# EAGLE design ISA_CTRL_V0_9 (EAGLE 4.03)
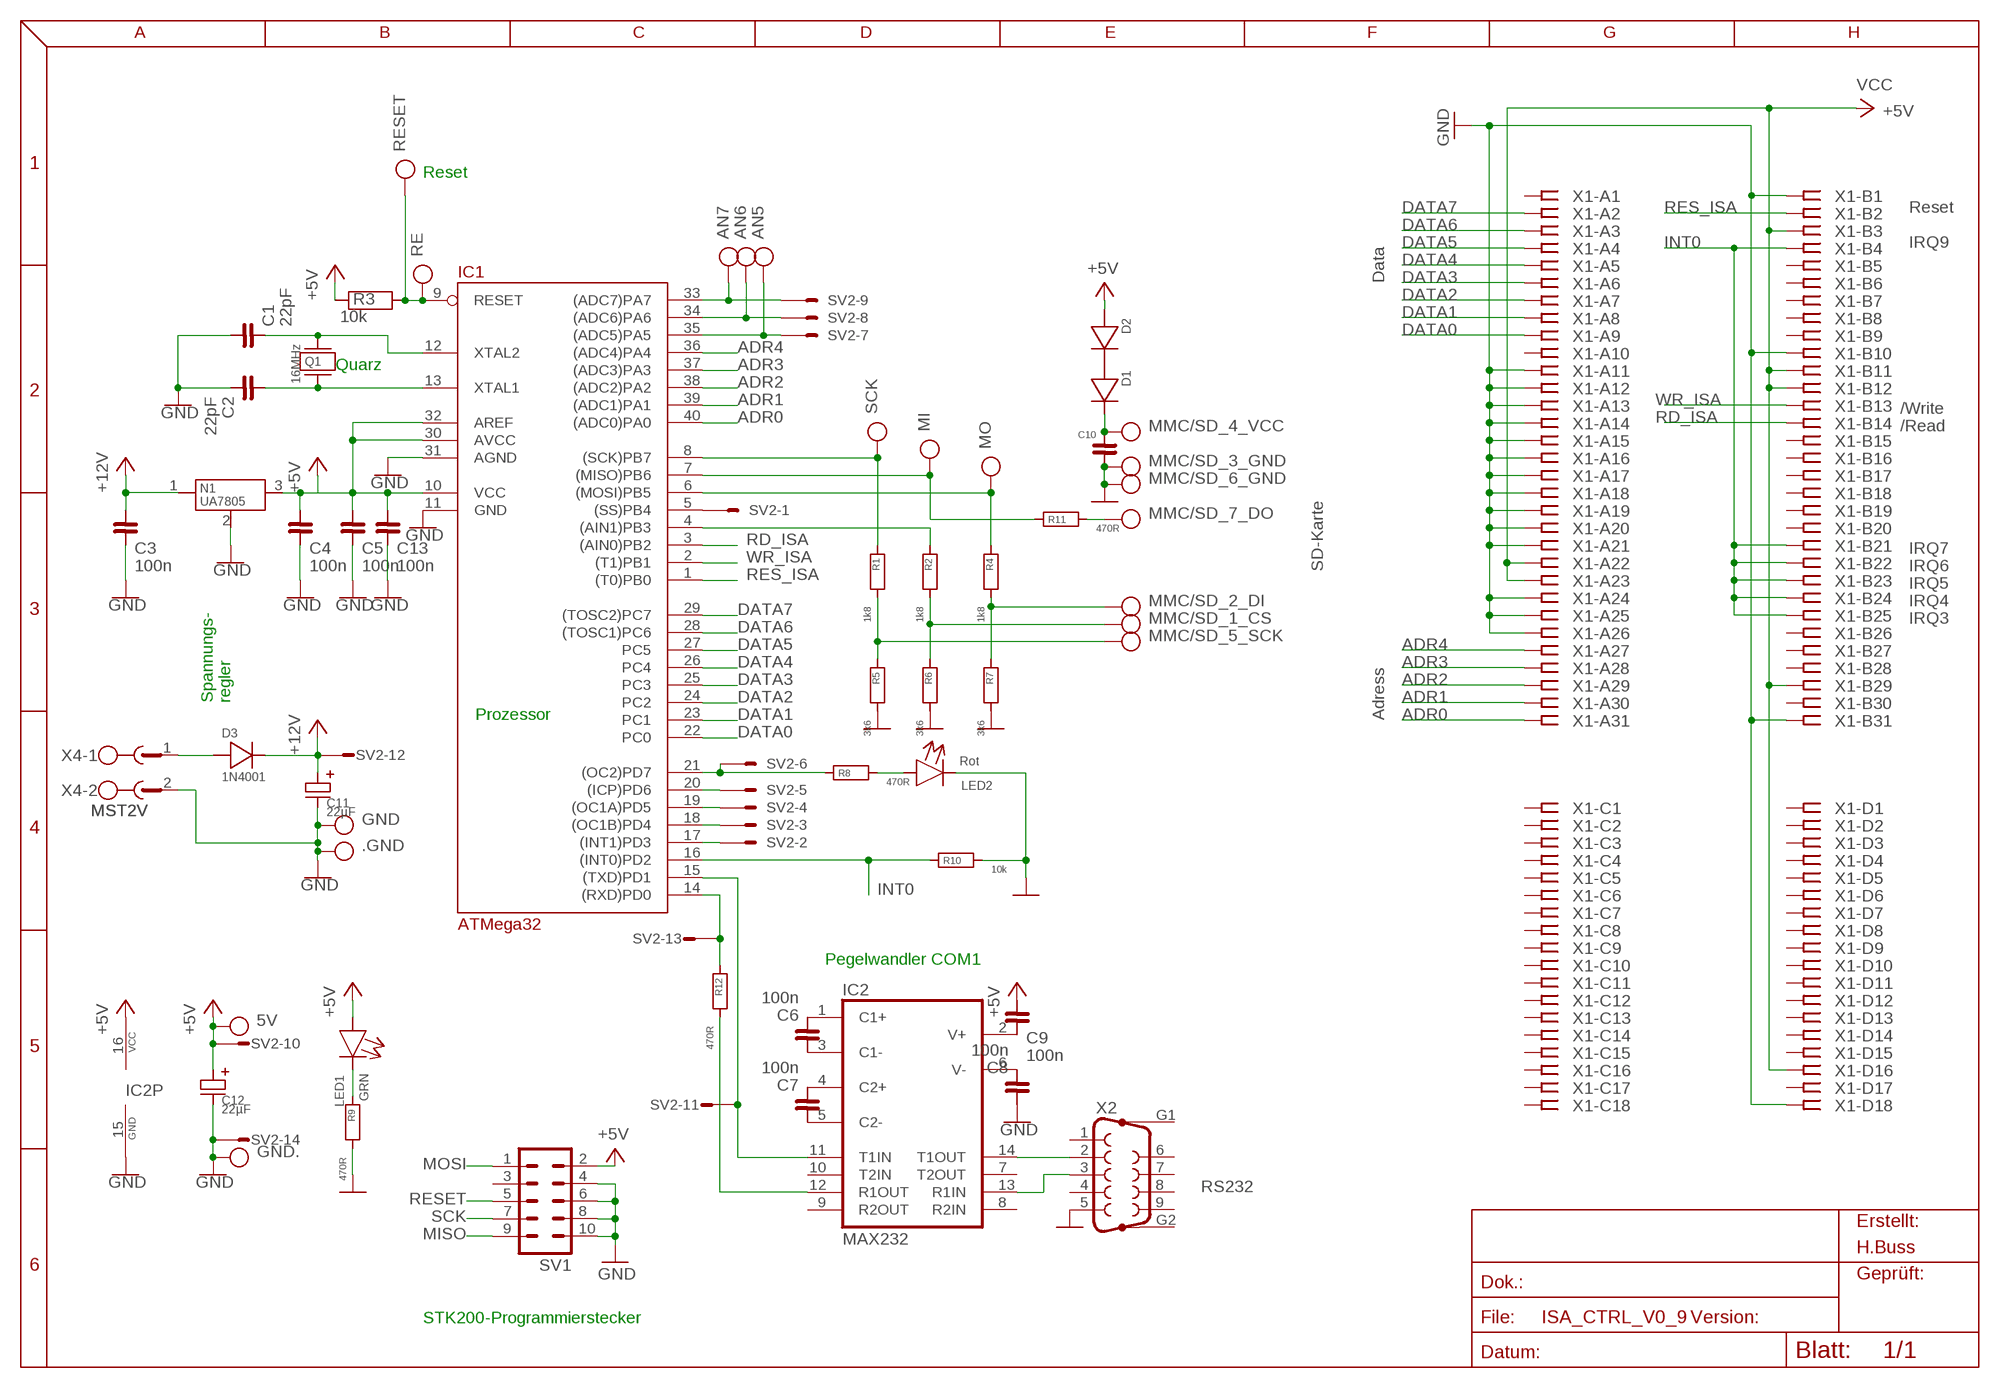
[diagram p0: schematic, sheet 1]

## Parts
5V  PIN_10  [PAD_10]
.GND  PIN_10  [PAD_10]
AN5  PIN_10  [PAD_10]
AN6  PIN_10  [PAD_10]
AN7  PIN_10  [PAD_10]
C1  22pF  C-2,5-MINI  [C-2,5]
C2  22pF  C-2,5-MINI  [C-2,5]
C3  100n  C-5,0  [C-5,0]
C4  100n  C-5,0  [C-5,0]
C5  100n  C-5,0  [C-5,0]
C6  100n  C-5,0  [C-5,0]
C7  100n  C-5,0  [C-5,0]
C8  100n  C-5,0  [C-5,0]
C9  100n  C-5,0  [C-5,0]
C10  C-5,0  [C-5,0]
C11  22µF  2,5-ELKO  [C-2,5-EL]
C12  22µF  2,5-ELKO  [C-2,5-EL]
C13  100n  C-5,0  [C-5,0]
D1  D-10  [D-10]
D2  D-10  [D-10]
D3  1N4001  D-10-1MM  [D-10-1MM]
GND  PIN_08  [PAD_08]
GND.  PIN_10  [PAD_10]
IC1  ATMega32  90S4434-P  [DIL40]
IC2  MAX232  [DIL16]
LED1  GRN  LED_5  [LED_5]
LED2  Rot  LED_5  [LED_5]
MI  PIN_10  [PAD_10]
MMC/SD_1_CS  PIN_081MM  [PAD_10]
MMC/SD_2_DI  PIN_081MM  [PAD_10]
MMC/SD_3_GND  PIN_081MM  [PAD_10]
MMC/SD_4_VCC  PIN_081MM  [PAD_10]
MMC/SD_5_SCK  PIN_081MM  [PAD_10]
MMC/SD_6_GND  PIN_081MM  [PAD_10]
MMC/SD_7_DO  PIN_081MM  [PAD_10]
MO  PIN_10  [PAD_10]
N1  UA7805  UA78XXLIEG  [TO220H]
Q1  16MHz  XTAL-HC18V  [HC-18-V]
R1  1k8  R-10  [R-10]
R2  1k8  R-10  [R-10]
R3  10k  R-10  [R-10]
R4  1k8  R-10  [R-10]
R5  3k6  R-10  [R-10]
R6  3k6  R-10  [R-10]
R7  3k6  R-10  [R-10]
R8  470R  R-10  [R-10]
R9  470R  R-10  [R-10]
R10  10k  R-10  [R-10]
R11  470R  R-10  [R-10]
R12  470R  R-10  [R-10]
RE  PIN_10  [PAD_10]
RESET  PIN_08  [PAD_08]
SCK  PIN_10  [PAD_10]
SV1  ML10  [ML10]
SV2  ML14E  [ML14]
X1  ISA-SLOT  [ISA-16]
X2  F09HP  [F09HP]
X4  MST2V  [MSTBV2]

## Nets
+5V: 5V.P$1(P) C4.P$2 C5.P$2 C9.P$2 C12.MINUS(PLUS) C13.P$2 D2.P$1 IC1.10(VCC) IC1.30(AVCC) IC1.32(AREF) IC2.16(VCC) LED1.A N1.3 R3.P$1 SV1.2 SV2.10 X1.A22 X1.A23 X1.B3 X1.B11 X1.B12 X1.B29 X1.D16 ; supply symbol labelled VCC
+12V: C3.P$2 C11.MINUS(PLUS) D3.P$2 N1.1 SV2.12
ADR0: IC1.40((ADC0)PA0) X1.A31
ADR1: IC1.39((ADC1)PA1) X1.A30
ADR2: IC1.38((ADC2)PA2) X1.A29
ADR3: IC1.37((ADC3)PA3) X1.A28
ADR4: IC1.36((ADC4)PA4) X1.A27
DATA0: IC1.22(PC0) X1.A9
DATA1: IC1.23(PC1) X1.A8
DATA2: IC1.24(PC2) X1.A7
DATA3: IC1.25(PC3) X1.A6
DATA4: IC1.26(PC4) X1.A5
DATA5: IC1.27(PC5) X1.A4
DATA6: IC1.28((TOSC1)PC6) X1.A3
DATA7: IC1.29((TOSC2)PC7) X1.A2
GND: .GND.P$1(P) C1.P$2 C2.P$1 C3.P$1 C4.P$1 C5.P$1 C8.P$2 C10.P$2 C11.PLUS C12.PLUS C13.P$1 GND..P$1(P) GND.P$1(P) IC1.11(GND) IC1.31(AGND) IC2.15(GND) LED2.K MMC/SD_3_GND.P$1(P) MMC/SD_6_GND.P$1(P) N1.2 R5.P$2 R6.P$2 R7.P$2 R9.P$2 R10.P$2 SV1.4 SV1.6 SV1.8 SV1.10 SV2.14 X1.A11 X1.A12 X1.A13 X1.A14 X1.A15 X1.A16 X1.A17 X1.A18 X1.A19 X1.A20 X1.A21 X1.A24 X1.A25 X1.A26 X1.B1 X1.B10 X1.B31 X1.D18 X2.5 X4.2
INT0: IC1.16((INT0)PD2) R10.P$1 X1.B4 X1.B21 X1.B22 X1.B23 X1.B24 X1.B25
MISO: IC1.7((MISO)PB6) MI.P$1(P) R11.P$1 SV1.9
MOSI: IC1.6((MOSI)PB5) MO.P$1(P) R4.P$1 SV1.1
N$1: C10.P$1 D1.P$2 MMC/SD_4_VCC.P$1(P)
N$2: MMC/SD_2_DI.P$1(P) R4.P$2 R7.P$1
N$3: MMC/SD_5_SCK.P$1(P) R1.P$2 R5.P$1
N$4: IC1.4((AIN1)PB3) R2.P$1
N$5: MMC/SD_1_CS.P$1(P) R2.P$2 R6.P$1
N$6: D1.P$1 D2.P$2
N$7: LED1.K R9.P$1
N$8: LED2.A R8.P$2
N$9: MMC/SD_7_DO.P$1(P) R11.P$2
N$10: IC1.17((INT1)PD3) SV2.2
N$11: AN5.P$1(P) IC1.35((ADC5)PA5) SV2.7
N$12: AN6.P$1(P) IC1.34((ADC6)PA6) SV2.8
N$13: AN7.P$1(P) IC1.33((ADC7)PA7) SV2.9
N$14: IC1.18((OC1B)PD4) SV2.3
N$15: IC1.5((SS)PB4) SV2.1
N$16: IC1.21((OC2)PD7) R8.P$1 SV2.6
N$17: IC1.19((OC1A)PD5) SV2.4
N$18: IC1.20((ICP)PD6) SV2.5
N$33: IC2.12(R1OUT) R12.P$2
N$34: C2.P$2 IC1.13(XTAL1) Q1.2
N$35: C1.P$1 IC1.12(XTAL2) Q1.1
N$36: IC2.14(T1OUT) X2.2
N$37: IC2.13(R1IN) X2.3
N$47: C6.P$1 IC2.1(C1+)
N$48: C6.P$2 IC2.3(C1-)
N$49: C7.P$1 IC2.4(C2+)
N$50: C7.P$2 IC2.5(C2-)
N$51: C8.P$1 IC2.6(V-)
N$52: C9.P$1 IC2.2(V+)
N$68: D3.P$1 X4.1
RD_ISA: IC1.3((AIN0)PB2) X1.B14
RES_ISA: IC1.1((T0)PB0) X1.B2
RESET: IC1.9(RESET) R3.P$2 RE.P$1(P) RESET.P$1(P) SV1.5
RXD: IC1.14((RXD)PD0) R12.P$1 SV2.13
SCK: IC1.8((SCK)PB7) R1.P$1 SCK.P$1(P) SV1.7
TXD: IC1.15((TXD)PD1) IC2.11(T1IN) SV2.11
WR_ISA: IC1.2((T1)PB1) X1.B13
Unconnected: IC2.7(T2OUT) IC2.8(R2IN) IC2.9(R2OUT) IC2.10(T2IN) SV1.3 X1.A1 X1.A10 X1.B5 X1.B6 X1.B7 X1.B8 X1.B9 X1.B15 X1.B16 X1.B17 X1.B18 X1.B19 X1.B20 X1.B26 X1.B27 X1.B28 X1.B30 X1.C1 X1.C2 X1.C3 X1.C4 X1.C5 X1.C6 X1.C7 X1.C8 X1.C9 X1.C10 X1.C11 X1.C12 X1.C13 X1.C14 X1.C15 X1.C16 X1.C17 X1.C18 X1.D1 X1.D2 X1.D3 X1.D4 X1.D5 X1.D6 X1.D7 X1.D8 X1.D9 X1.D10 X1.D11 X1.D12 X1.D13 X1.D14 X1.D15 X1.D17 X2.1 X2.4 X2.6 X2.7 X2.8 X2.9 X2.G1 X2.G2

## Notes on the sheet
- Reset
- Reset
- IRQ9
- Data
- Quarz
- /Write
- /Read
- IRQ7
- SD-Karte | IRQ6
- IRQ5
- IRQ4
- IRQ3
- Spannungs- | regler
- Prozessor | Adress
- Pegelwandler COM1
- RS232
- STK200-Programmierstecker

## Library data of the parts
5V .GND AN5-AN7 GND. = 0MY_STD_LIB:PIN_10
C1 C2 = MY_STD_L:C-2,5-MINI
C3-C9 C13 = MY_STD_L:C-5,0
C10 = 0MY_STD_LIB:C-5,0
C11 C12 = MY_STD_L:2,5-ELKO
D1 D2 = 0MY_STD_LIB:D-10
D3 = MY_STD_L:D-10-1MM
GND MMC/SD_1_CS MMC/SD_2_DI MMC/SD_3_GND MMC/SD_4_VCC MMC/SD_5_SCK MMC/SD_6_GND MMC/SD_7_DO = 0MY_STD_LIB:PIN_08
IC1 = ATMEL_:90S4434-P
IC2 = MAXIM:MAX232
LED1 LED2 = 0MY_STD_LIB:LED_5
MI MO RE SCK = MY_STD_L:PIN_10
N1 = MY_STD_L:UA78XXLIEG
Q1 = MY_STD_L:XTAL-HC18V
R1 R2 R4-R12 = 0MY_STD_LIB:R-10
R3 = MY_STD_L:R-10
RESET = MY_STD_L:PIN_08
SV1 = CON-ML:ML10
SV2 = CON-ML:ML14E
X1 = con-pc:ISA-SLOT: ISA SLOT
X2 = con-subd:F09HP: HARTING SUB-D
X4 = con-phoenix-508:MST2V: PHOENIX

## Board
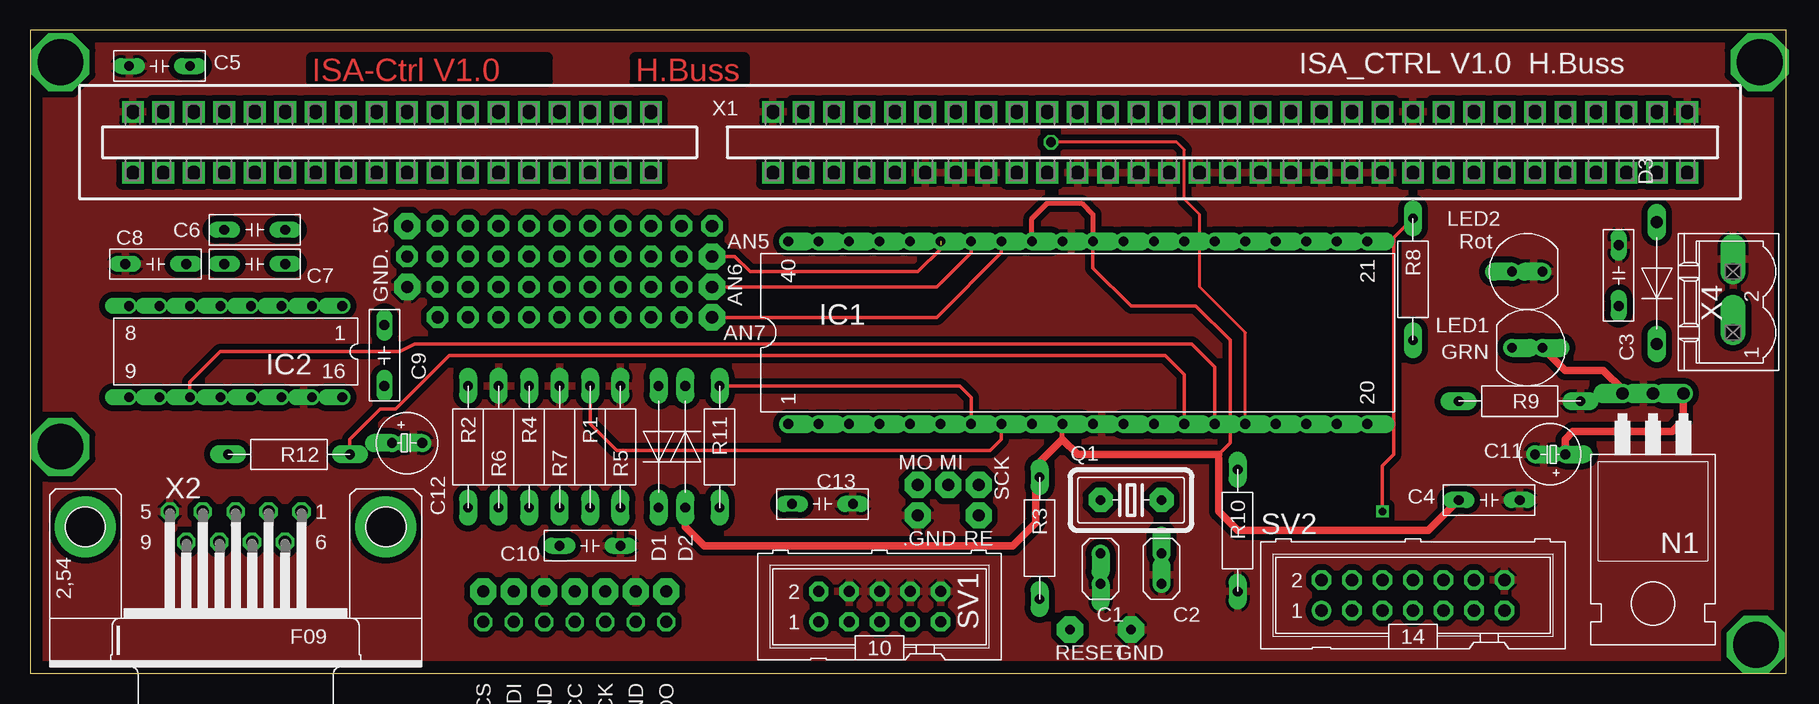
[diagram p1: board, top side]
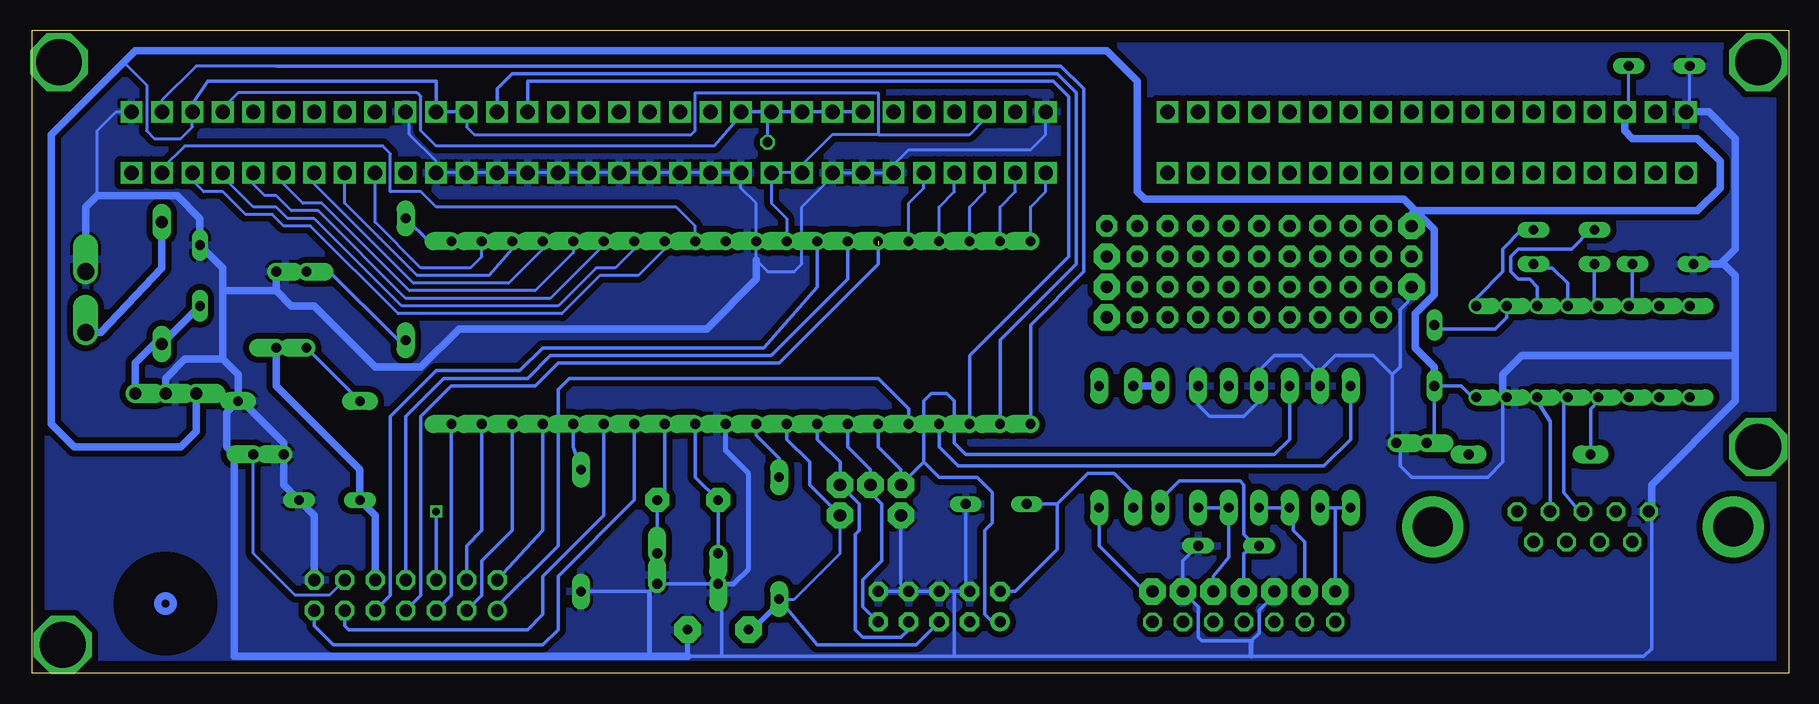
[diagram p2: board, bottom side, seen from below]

Size 146.35 x 53.64 mm. Coordinates in mm from the lower left corner, seen from the top.
Outline: 0,0 146.35,0 146.35,53.64 0,53.64 0,0
Copper layers used: Top, Bottom

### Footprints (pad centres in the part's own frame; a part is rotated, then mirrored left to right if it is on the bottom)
PAD_10 = drill 1.016 pad 2.184 octagon: P$1 0,0
C-2,5 = drill 0.813 pad 1.5 offset: P$1 0,0; P$2 2.54,0
C-5,0 = drill 0.813 pad 1.27 long: P$1 0,0; P$2 5.08,0
C-2,5-EL = drill 0.813 pad 1.5 offset: MINUS 2.54,0; PLUS 0,0
D-10 = drill 0.813 pad 1.5 long: P$1 0,0; P$2 10.16,0
D-10-1MM = drill 1.016 pad 1.5 long: P$1 -1.27,0; P$2 8.89,0
PAD_08 = drill 0.813 pad 2.184 octagon: P$1 0,0
DIL40 = drill 0.813 pad 1.5 offset: 1 -24.13,-7.62; 2 -21.59,-7.62; 3 -19.05,-7.62; 4 -16.51,-7.62; 5 -13.97,-7.62; 6 -11.43,-7.62; 7 -8.89,-7.62; 8 -6.35,-7.62; 9 -3.81,-7.62; 10 -1.27,-7.62; 11 1.27,-7.62; 12 3.81,-7.62; 13 6.35,-7.62; 14 8.89,-7.62; 15 11.43,-7.62; 16 13.97,-7.62; 17 16.51,-7.62; 18 19.05,-7.62; 19 21.59,-7.62; 20 24.13,-7.62; 21 24.13,7.62; 22 21.59,7.62; 23 19.05,7.62; 24 16.51,7.62; 25 13.97,7.62; 26 11.43,7.62; 27 8.89,7.62; 28 6.35,7.62; 29 3.81,7.62; 30 1.27,7.62; 31 -1.27,7.62; 32 -3.81,7.62; 33 -6.35,7.62; 34 -8.89,7.62; 35 -11.43,7.62; 36 -13.97,7.62; 37 -16.51,7.62; 38 -19.05,7.62; 39 -21.59,7.62; 40 -24.13,7.62
DIL16 = drill 0.813 pad 1.27 offset: 1 -8.89,-3.81; 2 -6.35,-3.81; 3 -3.81,-3.81; 4 -1.27,-3.81; 5 1.27,-3.81; 6 3.81,-3.81; 7 6.35,-3.81; 8 8.89,-3.81; 9 8.89,3.81; 10 6.35,3.81; 11 3.81,3.81; 12 1.27,3.81; 13 -1.27,3.81; 14 -3.81,3.81; 15 -6.35,3.81; 16 -8.89,3.81
LED_5 = drill 0.813 pad 1.5 offset: A 1.27,0; K -1.27,0
TO220H = drill 1.016 pad 1.626 offset: 1 0,0; 2 2.54,0; 3 5.08,0
HC-18-V = drill 0.813 pad 2 octagon: 1 0,0; 2 5.08,0
R-10 = drill 0.813 pad 1.5 long: P$1 0,0; P$2 10.16,0
ML10 = drill 0.914 pad 1.6 round: 1 -5.08,-1.27 | drill 0.914 pad 1.6 octagon: 2 -5.08,1.27; 3 -2.54,-1.27; 4 -2.54,1.27; 5 0,-1.27; 6 0,1.27; 7 2.54,-1.27; 8 2.54,1.27; 9 5.08,-1.27; 10 5.08,1.27
ML14 = drill 1.016 pad 1.6 round: 1 -7.62,-1.27 | drill 1.016 pad 1.6 octagon: 2 -7.62,1.27; 3 -5.08,-1.27; 4 -5.08,1.27; 5 -2.54,-1.27; 6 -2.54,1.27; 7 0,-1.27; 8 0,1.27; 9 2.54,-1.27; 10 2.54,1.27; 11 5.08,-1.27; 12 5.08,1.27; 13 7.62,-1.27; 14 7.62,1.27
ISA-16 = drill 1.2 pad 1.778 square: A1 81.28,-2.54; A2 78.74,-2.54; A3 76.2,-2.54; A4 73.66,-2.54; A5 71.12,-2.54; A6 68.58,-2.54; A7 66.04,-2.54; A8 63.5,-2.54; A9 60.96,-2.54; A10 58.42,-2.54; A11 55.88,-2.54; A12 53.34,-2.54; A13 50.8,-2.54; A14 48.26,-2.54; A15 45.72,-2.54; A16 43.18,-2.54; A17 40.64,-2.54; A18 38.1,-2.54; A19 35.56,-2.54; A20 33.02,-2.54; A21 30.48,-2.54; A22 27.94,-2.54; A23 25.4,-2.54; A24 22.86,-2.54; A25 20.32,-2.54; A26 17.78,-2.54; A27 15.24,-2.54; A28 12.7,-2.54; A29 10.16,-2.54; A30 7.62,-2.54; A31 5.08,-2.54; B1 81.28,2.54; B2 78.74,2.54; B3 76.2,2.54; B4 73.66,2.54; B5 71.12,2.54; B6 68.58,2.54; B7 66.04,2.54; B8 63.5,2.54; B9 60.96,2.54; B10 58.42,2.54; B11 55.88,2.54; B12 53.34,2.54; B13 50.8,2.54; B14 48.26,2.54; B15 45.72,2.54; B16 43.18,2.54; B17 40.64,2.54; B18 38.1,2.54; B19 35.56,2.54; B20 33.02,2.54; B21 30.48,2.54; B22 27.94,2.54; B23 25.4,2.54; B24 22.86,2.54; B25 20.32,2.54; B26 17.78,2.54; B27 15.24,2.54; B28 12.7,2.54; B29 10.16,2.54; B30 7.62,2.54; B31 5.08,2.54; C1 -5.08,-2.54; C2 -7.62,-2.54; C3 -10.16,-2.54; C4 -12.7,-2.54; C5 -15.24,-2.54; C6 -17.78,-2.54; C7 -20.32,-2.54; C8 -22.86,-2.54; C9 -25.4,-2.54; C10 -27.94,-2.54; C11 -30.48,-2.54; C12 -33.02,-2.54; C13 -35.56,-2.54; C14 -38.1,-2.54; C15 -40.64,-2.54; C16 -43.18,-2.54; C17 -45.72,-2.54; C18 -48.26,-2.54; D1 -5.08,2.54; D2 -7.62,2.54; D3 -10.16,2.54; D4 -12.7,2.54; D5 -15.24,2.54; D6 -17.78,2.54; D7 -20.32,2.54; D8 -22.86,2.54; D9 -25.4,2.54; D10 -27.94,2.54; D11 -30.48,2.54; D12 -33.02,2.54; D13 -35.56,2.54; D14 -38.1,2.54; D15 -40.64,2.54; D16 -43.18,2.54; D17 -45.72,2.54; D18 -48.26,2.54
F09HP = drill 1.016 octagon: 1 -5.486,-1.27; 2 -2.743,-1.27; 3 0,-1.27; 4 2.743,-1.27; 5 5.486,-1.27; 6 -4.115,1.27; 7 -1.372,1.27; 8 1.372,1.27; 9 4.115,1.27 | drill 3.302 pad 5.08 round: G1 -12.522,0; G2 12.522,0
MSTBV2 = drill 1.397 offset: 1 -2.54,0; 2 2.54,0

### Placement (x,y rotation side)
5V  31.43,37.3 0 top
.GND  73.97,13.17 0 top
AN5  56.83,34.76 0 top
AN6  56.83,32.22 0 top
AN7  56.83,29.68 0 top
C1  89.21,9.99 270 top
C2  94.29,7.45 90 top
C3  132.39,35.71 270 top
C4  124.14,14.44 180 top
C5  8.25,50.64 0 top
C6  21.27,36.98 180 top
C7  21.27,34.12 180 top
C8  13.01,34.12 180 top
C9  29.52,29.05 270 top
C10  44.13,10.63 0 top
C11  125.41,18.25 0 top
C12  32.7,19.2 180 top
C13  68.58,14.12 180 top
D1  52.38,23.97 270 top
D2  54.61,13.8 90 top
D3  135.57,36.35 270 top
GND  91.75,3.64 0 top
GND.  31.43,32.22 0 top
IC1  87.31,28.41 0 top
IC2  17.14,26.82 180 top
LED1  124.77,27.14 0 top
LED2  124.77,33.49 180 top
MI  76.51,15.71 180 top
MMC/SD_1_CS  37.78,6.82 0 top
MMC/SD_2_DI  40.32,6.82 270 top
MMC/SD_3_GND  42.86,6.82 270 top
MMC/SD_4_VCC  45.4,6.82 270 top
MMC/SD_5_SCK  47.94,6.82 270 top
MMC/SD_6_GND  50.48,6.82 270 top
MMC/SD_7_DO  53.02,6.82 270 top
MO  73.97,15.71 180 top
N1  137.79,23.33 180 top
Q1  89.21,14.44 0 top
R1  46.67,23.97 270 top
R2  36.51,23.97 270 top
R3  84.13,16.34 270 top
R4  41.59,23.97 270 top
R5  49.21,13.8 90 top
R6  39.05,13.8 90 top
R7  44.13,13.8 90 top
R8  115.25,37.94 270 top
R9  119.06,22.69 0 top
R10  100.64,16.98 270 top
R11  57.46,23.97 270 top
R12  26.67,18.25 180 top
RE  79.05,13.17 0 top
RESET  86.67,3.64 0 top
SCK  79.05,15.71 90 top
SV1  70.8,5.55 0 top
SV2  115.25,6.5 0 top
X1  56.83,44.28 0 top
X2  17.14,12.22 180 top
X4  141.92,30.95 90 top

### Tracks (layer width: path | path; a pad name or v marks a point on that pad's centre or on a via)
+5V
  Top 0.305: 99.06,18.25 100.01,19.2 100.01,27.78 97.15,30.63 91.75,30.63 88.58,33.81 IC1.30
  Top 0.406: IC1.32 83.5,37.94 84.77,39.2 87.62,39.2 88.58,38.25 IC1.30 | 86.04,19.52 IC1.10
  Top 0.61: 99.06,18.25 87.31,18.25 86.04,19.52 84.13,17.61 R3.P$1 83.81,16.03 83.81,12.53 81.91,10.63 56.19,10.63 54.61,12.22 D2.P$1 54.61,14.12 | N1.3 132.71,23.65 131.12,25.23 127.95,25.23 LED1.A | 99.06,17.93 99.06,13.49 100.64,11.9 116.52,11.9 C4.P$2
  Bottom 0.254: X1.B29 66.99,46.19 68.26,44.92 75.88,44.92 | 75.88,44.92 79.69,44.92 82.23,42.38 X1.A23 X1.A22 | X1.A22 84.77,39.2 83.5,37.94 IC1.32 | X1.A22 85.4,41.75 | 75.88,44.92 75.88,48.41 91.12,48.41 91.12,45.24 91.43,44.92 109.53,44.92 110.17,45.55 X1.B12 | 138.74,50.95 136.84,49.05 136.84,45.24 136.2,44.6 133.98,44.6 133.03,45.55 X1.B3 | C5.P$2 13.33,47.14 X1.D16
  Bottom 0.305: X1.B12 X1.B11 112.71,49.36 131.76,49.36 133.03,47.46 X1.B3 | IC2.16 26.03,22.69 27.3,23.97 C9.P$2 29.52,19.84 C12.MINUS | D2.P$1 54.61,15.07 56.19,16.66 58.42,16.66 60.95,14.12 | 60.95,14.12 60.95,10.31 64.45,6.82 SV1.2 | R3.P$1 84.13,17.93 86.04,19.84 IC1.10 | 60.95,14.12 C13.P$2
  Bottom 0.61: X1.D16 13.65,45.24 13.01,44.6 7.62,44.6 5.71,42.7 5.71,40.47 7.62,38.57 31.11,38.57 | 31.11,38.57 32.06,39.52 53.65,39.52 54.29,40.16 54.29,49.36 56.83,51.91 137.79,51.91 138.74,50.95 144.77,44.92 144.77,20.79 142.87,18.89 133.98,18.89 132.71,20.16 N1.3 | SV2.10 117.79,13.17 C4.P$2 119.06,16.98 126.04,23.97 LED1.A | C9.P$2 29.52,25.55 31.11,27.14 31.11,30 29.52,31.58 29.52,36.98 31.11,38.57 | 5V.P$1 31.75,37.94 31.11,38.57
+12V
  Top 0.61: C11.MINUS 127.95,19.52 128.58,20.16 136.84,20.16 137.79,21.11 N1.1
  Bottom 0.254: C11.MINUS 127.95,9.99 124.45,6.5 121.6,6.5 SV2.12
  Bottom 0.61: C3.P$2 D3.P$2 136.2,27.46 137.79,25.87 N1.1
ADR0
  Bottom 0.254: X1.A31 61.91,40.16 63.18,38.89 IC1.40
ADR1
  Bottom 0.254: X1.A30 64.45,40.16 65.72,38.89 IC1.39
ADR2
  Bottom 0.254: X1.A29 66.99,40.16 68.26,38.89 IC1.38
ADR3
  Bottom 0.254: X1.A28 69.53,40.16 70.8,38.89 IC1.37
ADR4
  Bottom 0.254: X1.A27 72.07,40.47 73.34,39.2 IC1.36
DATA0
  Bottom 0.254: IC1.22 108.9,34.76 109.85,33.81 113.98,33.81 117.79,37.62 X1.A9
DATA1
  Bottom 0.254: IC1.23 106.36,35.39 108.26,33.17 114.29,33.17 120.33,39.2 X1.A8
DATA2
  Bottom 0.254: IC1.24 103.82,35.39 106.67,32.54 114.61,32.54 122.87,40.79 X1.A7
DATA3
  Bottom 0.254: IC1.25 101.28,35.08 104.45,31.9 114.93,31.9 122.23,39.2 123.82,39.2 125.41,40.79 X1.A6
DATA4
  Bottom 0.254: IC1.26 98.74,35.71 103.18,31.27 115.25,31.27 122.55,38.57 124.77,38.57 126.04,39.84 126.99,39.84 127.95,40.79 X1.A5
DATA5
  Bottom 0.254: IC1.27 96.2,35.39 97.79,33.81 99.37,33.81 102.55,30.63 115.57,30.63 122.87,37.94 125.09,37.94 126.04,38.89 127.95,38.89 130.49,41.43 X1.A4
DATA6
  Bottom 0.254: IC1.28 93.66,35.39 95.88,33.17 99.06,33.17 102.23,30 115.88,30 123.19,37.3 125.41,37.3 126.36,38.25 128.58,38.25 130.49,40.16 132.07,40.16 133.03,41.11 X1.A3
DATA7
  Bottom 0.254: IC1.29 91.12,37.3 92.7,38.89 112.71,38.89 113.98,40.16 116.52,40.16 116.52,43.33 117.15,43.97 133.66,43.97 135.57,42.06 X1.A2
GND
  Bottom 0.254: X1.B31 61.91,44.92 63.18,43.65 73.34,43.65 74.61,42.38 X1.A26 X1.A25 X1.A24 | X1.A24 79.69,41.11 | X1.B10 114.93,46.51 114.93,44.92 112.71,42.7 X1.A11 X1.A12 X1.A13 X1.A14 X1.A15 | X1.B1 139.38,46.83 140.97,45.24 140.97,39.84 | X1.A24 79.69,41.43 82.23,38.89 82.23,34.12 82.86,33.49 85.09,33.49 86.04,34.44 IC1.31 86.04,39.2 87.31,40.47 X1.A21 X1.A20 X1.A19 X1.A18 X1.A17 X1.A16 X1.A15 | X1.A15 102.87,41.75 | C5.P$1 8.25,47.14 X1.D18
  Bottom 0.305: R10.P$2 94.93,6.82 C2.P$1 C1.P$2 88.9,7.14 88.9,1.42 | 69.53,6.82 SV1.6 SV1.8 | SV1.8 SV1.10 | .GND.P$1 73.97,7.45 SV1.8 | 69.53,6.82 SV1.4 68.57,7.14 C13.P$1 | 69.53,1.42 69.53,6.82 | 69.53,1.42 88.9,1.42 | 69.53,1.42 44.76,1.42 12.06,1.42 11.43,2.06 11.43,14.12 | IC2.15 23.81,23.01 23.81,17.61 25.08,16.34 31.43,16.34 32.38,17.3 32.38,18.89 C12.PLUS 33.01,19.52 33.01,24.92 | MMC/SD_3_GND.P$1 42.86,6.5 44.13,5.23 44.13,3.33 44.76,2.69 48.89,2.69 49.21,3.01 49.21,5.55 MMC/SD_6_GND.P$1 50.48,9.36 C10.P$2 | R5.P$2 49.21,22.38 48.26,21.42 45.4,21.42 44.13,22.69 R7.P$2 44.13,25.23 42.86,26.5 40.64,26.5 39.05,24.92 R6.P$2 39.05,25.23 37.78,26.5 34.6,26.5 33.01,24.92 | 88.9,1.42 91.75,1.42 | GND..P$1 31.75,30.95 32.38,30.31 32.38,25.55 33.01,24.92
  Bottom 0.406: IC1.11 88.58,18.57 86.67,16.66 86.67,8.73 87.94,7.45 C1.P$2 | 91.75,1.42 GND.P$1 | 94.93,1.42 94.93,6.82 | 44.76,1.42 44.76,2.69
  Bottom 0.61: 5.71,34.12 5.39,34.12 4.44,33.17 4.44,26.5 | 5.71,34.12 C8.P$2 | 4.44,26.5 4.44,22.69 11.43,15.71 11.43,14.12 X2.5 | X1.D18 6.66,46.83 4.44,44.6 4.44,35.39 5.71,34.12 | 23.81,23.01 23.81,24.92 22.22,26.5 4.44,26.5 | R9.P$2 129.22,23.01 125.41,19.2 C11.PLUS 125.41,15.71 C4.P$1 122.87,13.17 SV2.14 | 130.49,26.19 130.49,31.9 | 130.49,26.19 133.66,26.19 135.25,24.6 N1.2 135.25,23.01 | R9.P$2 129.22,24.92 130.49,26.19 | R9.P$2 130.17,21.74 130.17,18.89 129.54,18.25 129.54,1.42 94.93,1.42 91.75,1.42 | 86.04,34.44 86.04,32.86 90.17,28.73 110.8,28.73 113.98,25.55 117.79,25.55 122.87,30.63 124.77,30.63 126.04,31.9 | 126.04,31.9 LED2.K | 130.49,31.9 126.04,31.9 | 130.49,31.9 130.49,33.81 C3.P$1 132.39,37.94 134.3,39.84 140.97,39.84 141.92,38.89 X4.2
  pour Top (isolate 0.5): 0.63,52.86 0.63,0.79 146.04,0.47 146.36,52.86
  pour Bottom (isolate 0.5): 0.63,52.86 0.63,0.79 145.73,0.79 146.04,52.86
INT0  (via drill 0.81)
  Top 0.254: IC1.16 101.28,28.41 97.47,32.22 97.47,38.25 96.2,39.52 96.2,43.65 95.56,44.28 v85.09,44.28
  Bottom 0.254: X1.B21 87.31,46.51 89.53,43.97 112.71,43.97 113.98,45.24 113.98,48.09 114.29,48.41 129.22,48.41 130.49,47.14 X1.B4 | v85.09,44.28 85.09,46.51 X1.B22
  Bottom 0.305: X1.B25 X1.B24 X1.B23 X1.B22 X1.B21 | R10.P$1 101.28,18.89 IC1.16
MISO
  Top 0.305: R11.P$1 77.46,23.97 78.42,23.01 IC1.7
  Bottom 0.305: IC1.7 78.42,18.89 76.51,16.98 MI.P$1 76.51,15.07 75.56,14.12 75.56,9.36 77.15,7.77 77.15,5.55 SV1.9
MOSI
  Bottom 0.305: IC1.6 75.88,18.89 73.97,16.98 MO.P$1 72.07,17.61 | SV1.1 66.35,4.28 66.99,4.91 66.99,11.9 66.35,12.53 66.35,15.07 67.62,16.34 70.8,16.34 72.07,17.61 | R4.P$1 41.59,19.52 42.86,18.25 68.57,18.25 69.53,19.2 69.53,22.69 70.16,23.33 71.43,23.33 72.07,22.69 72.07,17.61
N$1
  Bottom 0.305: D1.P$2 52.38,14.44 50.79,16.03 45.71,16.03 45.4,15.71 45.4,11.58 44.45,10.63 C10.P$1 45.4,9.99 MMC/SD_4_VCC.P$1
N$2
  Bottom 0.305: MMC/SD_2_DI.P$1 40.32,10.95 41.27,11.9 41.27,13.49 R4.P$2 R7.P$1
N$3
  Bottom 0.305: MMC/SD_5_SCK.P$1 47.94,8.09 46.67,9.68 R1.P$2 R5.P$1
N$4
  Bottom 0.305: R2.P$1 36.51,19.52 38.73,17.3 69.21,17.3 70.8,18.89 IC1.4
N$5
  Bottom 0.305: MMC/SD_1_CS.P$1 37.78,13.8 | 37.78,13.8 R2.P$2 | 37.78,13.8 R6.P$1
N$6
  Bottom 0.61: D1.P$1 D2.P$2
N$7
  Bottom 0.305: R9.P$1 LED1.K
N$8
  Bottom 0.305: R8.P$2 115.88,27.78 121.92,33.81 123.19,33.81 LED2.A
N$9
  Bottom 0.305: MMC/SD_7_DO.P$1 53.65,6.82 57.46,10.63 R11.P$2
N$10
  Bottom 0.305: IC1.17 103.82,11.9 SV2.2
N$11  (1 unrouted)
  Top 0.305: AN5.P$1 58.73,34.76 60,33.49 73.97,33.49 75.88,35.39 75.88,35.71
  Bottom 0.305: IC1.35 75.88,34.12 84.13,25.87 102.55,25.87 104.45,23.97 111.44,23.97 113.98,21.42 113.98,6.5 SV2.7
N$12
  Top 0.305: AN6.P$1 75.56,32.22 78.42,35.08 IC1.34
  Bottom 0.305: IC1.34 78.42,32.86 84.77,26.5 103.18,26.5 105.09,24.6 112.07,24.6 115.25,21.42 SV2.8
N$13
  Top 0.305: AN7.P$1 75.56,29.68 80.96,35.08 IC1.33
  Bottom 0.305: IC1.33 80.96,32.22 85.4,27.14 103.82,27.14 105.72,25.23 112.71,25.23 116.52,21.42 116.52,6.5 SV2.9
N$14
  Bottom 0.305: IC1.18 106.36,11.9 108.9,9.36 108.9,6.5 SV2.3
N$15
  Bottom 0.305: SV2.1 107.95,5.23 102.55,10.63 102.55,23.65 101.59,24.6 75.88,24.6 73.34,22.06 IC1.5
N$16  (via drill 0.61)
  Top 0.305: v112.71,13.49 112.71,17.3 113.66,18.25 113.66,36.35 R8.P$1
  Bottom 0.305: IC1.21 113.34,36.03 R8.P$1 | SV2.6 v112.71,13.49
N$17
  Bottom 0.305: IC1.19 108.9,11.9 110.17,10.63 SV2.4
N$18
  Bottom 0.305: IC1.20 111.44,6.5 SV2.5
N$19  (via drill 1.02)
  other vias: 37.78,4.28
N$20  (via drill 1.02)
  other vias: 40.32,4.28
N$21  (via drill 1.02)
  other vias: 42.86,4.28
N$22  (via drill 3.81 pad 1.78)
  other vias: 144.14,50.95
N$23  (via drill 1.02)
  other vias: 45.4,4.28
N$24  (via drill 1.02)
  other vias: 47.94,4.28
N$25  (via drill 1.02)
  other vias: 50.48,4.28
N$26  (via drill 1.02)
  other vias: 53.02,4.28
N$27  (via drill 3.81 pad 1.78)
  other vias: 143.82,2.38
N$28  (via drill 1.02 pad 1.78)
  other vias: 54.29,37.3
N$29  (via drill 1.02 pad 1.78)
  other vias: 33.97,37.3
N$30  (via drill 1.02 pad 1.78)
  other vias: 36.51,37.3
N$31  (via drill 1.02 pad 1.78)
  other vias: 39.05,37.3
N$32  (via drill 1.02 pad 1.78)
  other vias: 41.59,37.3
N$33
  Bottom 0.305: IC2.12 15.87,22.69 16.5,22.06 R12.P$2
N$34
  Bottom 0.305: IC1.13 93.66,15.07 Q1.2 C2.P$2
N$35
  Bottom 0.305: IC1.12 91.12,16.34 Q1.1 C1.P$1
N$36
  Bottom 0.305: IC2.14 20.95,22.69 19.88,20.99 X2.2
N$37
  Bottom 0.305: X2.3 17.46,13.49 18.73,15.07 18.73,22.38 18.41,22.69 IC2.13
N$38  (via drill 1.02 pad 1.78)
  other vias: 44.13,37.3
N$39  (via drill 1.02 pad 1.78)
  other vias: 46.67,37.3
N$40  (via drill 1.02 pad 1.78)
  other vias: 49.21,37.3
N$41  (via drill 1.02 pad 1.78)
  other vias: 51.75,37.3
N$42  (via drill 1.02 pad 1.78)
  other vias: 33.97,34.76
N$43  (via drill 1.02 pad 1.78)
  other vias: 36.51,34.76
N$44  (via drill 1.02 pad 1.78)
  other vias: 39.05,34.76
N$45  (via drill 1.02 pad 1.78)
  other vias: 41.59,34.76
N$46  (via drill 1.02 pad 1.78)
  other vias: 44.13,34.76
N$47
  Bottom 0.305: C6.P$1 22.22,36.98 23.81,35.39 23.81,33.49 26.03,31.27 IC2.1
N$48
  Bottom 0.305: C6.P$2 16.5,36.98 18.09,35.39 22.54,35.39 23.17,34.76 23.17,33.49 22.54,32.86 21.58,32.86 20.95,32.22 IC2.3
N$49
  Bottom 0.305: IC2.4 18.41,32.54 19.68,33.81 20.95,33.81 C7.P$1
N$50
  Bottom 0.305: C7.P$2 16.19,30.95 IC2.5
N$51
  Bottom 0.305: IC2.6 13.65,30.63 13.01,31.27 C8.P$1
N$52
  Bottom 0.305: IC2.2 23.49,29.68 24.44,28.73 29.21,28.73 C9.P$1
N$53  (via drill 1.02 pad 1.78)
  other vias: 46.67,34.76
N$54  (via drill 1.02 pad 1.78)
  other vias: 49.21,34.76
N$55  (via drill 1.02 pad 1.78)
  other vias: 51.75,34.76
N$56  (via drill 1.02 pad 1.78)
  other vias: 33.97,32.22
N$57  (via drill 1.02 pad 1.78)
  other vias: 36.51,32.22
N$58  (via drill 1.02 pad 1.78)
  other vias: 39.05,32.22
N$59  (via drill 1.02 pad 1.78)
  other vias: 41.59,32.22
N$60  (via drill 1.02 pad 1.78)
  other vias: 44.13,32.22
N$61  (via drill 1.02 pad 1.78)
  other vias: 46.67,32.22
N$62  (via drill 1.02 pad 1.78)
  other vias: 49.21,32.22
N$63  (via drill 1.02 pad 1.78)
  other vias: 51.75,32.22
N$64  (via drill 1.02 pad 1.78)
  other vias: 33.97,29.68
N$65  (via drill 1.02 pad 1.78)
  other vias: 36.51,29.68
N$66  (via drill 1.02 pad 1.78)
  other vias: 39.05,29.68
N$67  (via drill 1.02 pad 1.78)
  other vias: 41.59,29.68
N$68
  Bottom 0.61: D3.P$1 135.57,33.81 140.65,28.41 X4.1
N$69  (via drill 1.02 pad 1.78)
  other vias: 44.13,29.68
N$70  (via drill 1.02 pad 1.78)
  other vias: 46.67,29.68
N$71  (via drill 1.02 pad 1.78)
  other vias: 49.21,29.68
N$72  (via drill 1.02 pad 1.78)
  other vias: 51.75,29.68
N$73  (via drill 1.02 pad 1.78)
  other vias: 54.29,34.76
N$74  (via drill 1.02 pad 1.78)
  other vias: 54.29,32.22
N$75  (via drill 1.02 pad 1.78)
  other vias: 54.29,29.68
N$76  (via drill 3.81 pad 1.78)
  other vias: 2.54,50.95
N$77  (via drill 3.81 pad 1.78)
  other vias: 2.54,18.89
N$78  (via drill 1.02 pad 1.78)
  other vias: 56.83,37.3
N$79  (via drill 1.02 pad 1.78)
  other vias: 31.43,34.76
RD_ISA
  Bottom 0.305: IC1.3 68.26,26.5 60,34.76 60,48.09 61.27,49.36 105.09,49.36 X1.B14
RES_ISA
  Bottom 0.254: 126.04,50.64 132.71,50.64 135.57,47.78 X1.B2
  Bottom 0.305: IC1.1 63.18,29.05 58.73,33.49 58.73,48.73 60.64,50.64 126.04,50.64
RESET
  Bottom 0.254: R3.P$2 82.86,6.19 79.05,9.99 RE.P$1
  Bottom 0.305: IC1.9 83.5,19.52 81.59,17.61 81.59,15.71 RE.P$1 | SV1.5 72.7,2.38 80.96,2.38 R3.P$2
  Bottom 0.406: RESET.P$1 86.36,3.64 84.13,5.87 R3.P$2
RXD
  Top 0.305: IC1.14 96.2,24.92 94.61,26.5 34.92,26.5 30.47,22.06 29.21,22.06 26.67,19.52 R12.P$1
  Bottom 0.305: IC1.14 96.2,14.44 102.55,8.09 102.55,3.64 103.82,2.38 121.28,2.38 122.87,3.96 SV2.13
SCK
  Top 0.305: R1.P$1 46.67,20.79 48.89,18.57 80.01,18.57 80.96,19.52 IC1.8
  Bottom 0.305: IC1.8 80.96,19.52 79.05,17.61 SCK.P$1 77.46,14.12 77.46,11.9 77.78,11.58 77.78,3.64 77.15,3.01 73.97,3.01 73.34,3.64 SV1.7
TXD
  Top 0.305: IC1.15 98.74,25.55 96.83,27.46 32.06,27.46 30.79,26.82 15.87,26.82 13.33,24.28 IC2.11
  Bottom 0.305: IC1.15 98.74,13.17 103.82,8.09 103.82,4.91 105.09,3.64 120.01,3.64 120.33,3.96 SV2.11
WR_ISA
  Bottom 0.305: IC1.2 65.72,27.78 59.37,34.12 59.37,48.41 60.95,50 106.36,50 107.63,48.73 X1.B13

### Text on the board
Top: ISA-Ctrl V1.0 | H.Buss
tPlace: ISA_CTRL V1.0 H.Buss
